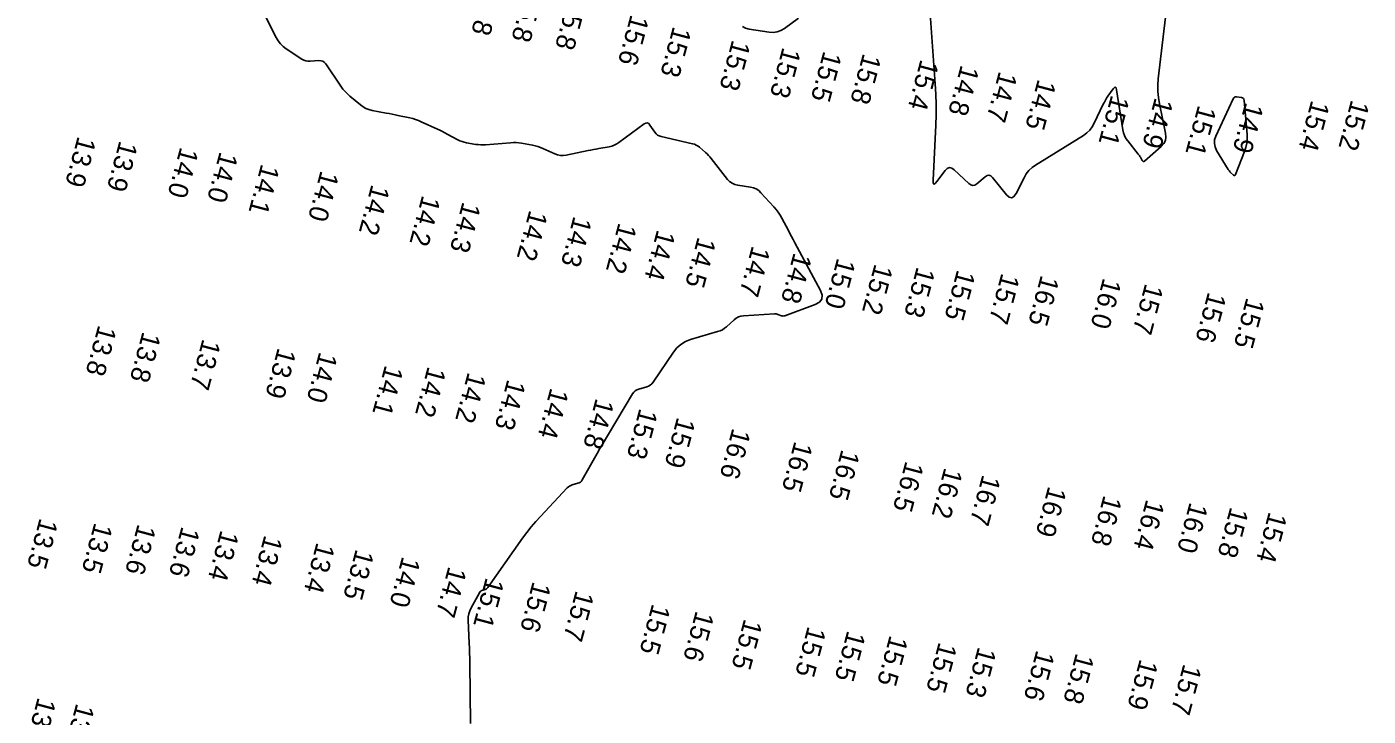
# Model space of a CAD drawing. Extents: x 988130 to 1132882, y 654656 to 841453.
# Drawn here: x 1028543.7 to 1028891.8, y 772126.1 to 772305 of the extents above; entities that cross this region are included whole.
import ezdxf

# ---------------------------------------------------------------- set-up
doc = ezdxf.new("R2010")
doc.units = 0
doc.layers.add('V-TOPO-MAJR', color=7, linetype='Continuous')
doc.layers.add('V-TOPO-SOUN', color=7, linetype='Continuous')

msp = doc.modelspace()

# ---------------------------------------------------------------- linework, layer by layer
at = {"layer": 'V-TOPO-MAJR'}
for points in [[(1028840.9, 772322.06), (1028837.3, 772291.48), (1028837.18, 772289.85), (1028837.19, 772288.22), (1028837.33, 772286.6), (1028837.6, 772284.98), (1028839.21, 772277.36), (1028839.3, 772276.38), (1028839.14, 772275.48), (1028838.73, 772274.67), (1028838.07, 772273.94), (1028833.74, 772270.14), (1028833.56, 772270.03), (1028833.4, 772270.01), (1028833.26, 772270.09), (1028833.13, 772270.26), (1028832.67, 772271.13), (1028832.55, 772271.35), (1028832.42, 772271.56), (1028832.28, 772271.76), (1028832.13, 772271.96), (1028829.38, 772275.38), (1028828.92, 772276.03), (1028828.56, 772276.73), (1028828.29, 772277.47), (1028828.12, 772278.25), (1028826.5, 772288.66), (1028826.38, 772289.11), (1028826.19, 772289.3), (1028825.94, 772289.22), (1028825.63, 772288.87), (1028824.24, 772286.95), (1028823.91, 772286.47), (1028823.6, 772285.97), (1028823.31, 772285.45), (1028823.05, 772284.92), (1028820.71, 772279.97), (1028820.18, 772279.02), (1028819.53, 772278.18), (1028818.76, 772277.43), (1028817.87, 772276.8), (1028805.47, 772269.11), (1028804.55, 772268.45), (1028803.74, 772267.68), (1028803.05, 772266.81), (1028802.47, 772265.83), (1028800.41, 772261.7), (1028799.86, 772260.91), (1028799.27, 772260.6), (1028798.62, 772260.77), (1028797.91, 772261.42), (1028794.29, 772265.87), (1028793.84, 772266.29), (1028793.37, 772266.46), (1028792.87, 772266.38), (1028792.35, 772266.06), (1028790.21, 772264.26), (1028789.68, 772263.93), (1028789.16, 772263.83), (1028788.64, 772263.96), (1028788.14, 772264.32), (1028784.36, 772267.89), (1028783.72, 772268.34), (1028783.11, 772268.46), (1028782.53, 772268.24), (1028781.98, 772267.69), (1028779.83, 772264.8), (1028779.37, 772264.29), (1028779.05, 772264.17), (1028778.88, 772264.46), (1028778.85, 772265.16), (1028779.57, 772279.44), (1028779.67, 772282.11), (1028779.68, 772284.79), (1028779.61, 772287.47), (1028779.45, 772290.14), (1028778.03, 772309.51)], [(1028602.75, 772313.44), (1028608.38, 772302.21), (1028608.89, 772301.35), (1028609.49, 772300.57), (1028610.18, 772299.89), (1028610.98, 772299.29), (1028615.09, 772296.6), (1028615.58, 772296.33), (1028616.1, 772296.15), (1028616.63, 772296.05), (1028617.19, 772296.05), (1028619.48, 772296.21), (1028620.02, 772296.18), (1028620.49, 772296.03), (1028620.91, 772295.75), (1028621.26, 772295.34), (1028625.22, 772289.53), (1028625.73, 772288.82), (1028626.29, 772288.16), (1028626.9, 772287.54), (1028627.55, 772286.96), (1028630.26, 772284.72), (1028630.95, 772284.21), (1028631.69, 772283.8), (1028632.48, 772283.49), (1028633.32, 772283.28), (1028636.93, 772282.61), (1028637.7, 772282.47), (1028638.47, 772282.32), (1028639.24, 772282.16), (1028640.01, 772282), (1028643.08, 772281.34), (1028643.84, 772281.16), (1028644.59, 772280.93), (1028645.32, 772280.66), (1028646.04, 772280.36), (1028650.24, 772278.42), (1028650.89, 772278.12), (1028651.53, 772277.8), (1028652.17, 772277.47), (1028652.81, 772277.14), (1028655.52, 772275.68), (1028656.07, 772275.41), (1028656.63, 772275.19), (1028657.22, 772275.01), (1028657.82, 772274.89), (1028660.25, 772274.48), (1028660.86, 772274.4), (1028661.47, 772274.36), (1028662.08, 772274.35), (1028662.69, 772274.38), (1028669.24, 772274.91), (1028669.95, 772274.95), (1028670.67, 772274.94), (1028671.38, 772274.88), (1028672.09, 772274.78), (1028674.92, 772274.27), (1028675.62, 772274.12), (1028676.31, 772273.93), (1028676.98, 772273.7), (1028677.64, 772273.42), (1028680.67, 772272.02), (1028681.4, 772271.75), (1028682.15, 772271.61), (1028682.91, 772271.58), (1028683.68, 772271.68), (1028689.37, 772272.86), (1028690.05, 772273), (1028690.73, 772273.13), (1028691.41, 772273.26), (1028692.1, 772273.38), (1028694.84, 772273.87), (1028695.51, 772274.03), (1028696.15, 772274.26), (1028696.76, 772274.57), (1028697.33, 772274.94), (1028703.88, 772279.76), (1028704.31, 772279.99), (1028704.7, 772280.02), (1028705.07, 772279.86), (1028705.39, 772279.49), (1028706.63, 772277.65), (1028706.97, 772277.23), (1028707.37, 772276.9), (1028707.82, 772276.65), (1028708.34, 772276.48), (1028716.47, 772274.64), (1028716.96, 772274.49), (1028717.43, 772274.29), (1028717.87, 772274.03), (1028718.27, 772273.71), (1028719.85, 772272.33), (1028720.23, 772271.98), (1028720.6, 772271.61), (1028720.95, 772271.22), (1028721.28, 772270.82), (1028725.53, 772265.4), (1028726.08, 772264.82), (1028726.7, 772264.37), (1028727.41, 772264.05), (1028728.19, 772263.86), (1028731.46, 772263.39), (1028732.24, 772263.2), (1028732.96, 772262.9), (1028733.62, 772262.47), (1028734.21, 772261.93), (1028737.57, 772258.25), (1028738.16, 772257.57), (1028738.69, 772256.86), (1028739.18, 772256.11), (1028739.63, 772255.33), (1028741.31, 772252.15), (1028741.73, 772251.35), (1028742.15, 772250.55), (1028742.58, 772249.76), (1028743, 772248.96), (1028749.63, 772236.53), (1028750.07, 772235.33), (1028749.98, 772234.32), (1028749.38, 772233.52), (1028748.26, 772232.91), (1028740.42, 772230.02), (1028740.19, 772229.96), (1028739.96, 772229.94), (1028739.74, 772229.96), (1028739.51, 772230.02), (1028738.61, 772230.36), (1028738.38, 772230.43), (1028738.15, 772230.48), (1028737.92, 772230.5), (1028737.68, 772230.5), (1028729.65, 772229.98), (1028728.99, 772229.88), (1028728.38, 772229.69), (1028727.81, 772229.39), (1028727.29, 772228.99), (1028725.27, 772227.18), (1028724.75, 772226.76), (1028724.19, 772226.4), (1028723.59, 772226.12), (1028722.96, 772225.89), (1028715.92, 772223.81), (1028714.6, 772223.3), (1028713.42, 772222.59), (1028712.39, 772221.69), (1028711.5, 772220.58), (1028706.2, 772212.79), (1028705.87, 772212.38), (1028705.49, 772212.04), (1028705.05, 772211.78), (1028704.56, 772211.59), (1028702.48, 772210.98), (1028702, 772210.78), (1028701.57, 772210.51), (1028701.2, 772210.17), (1028700.89, 772209.74), (1028694.61, 772199.26), (1028693.87, 772198.03), (1028693.14, 772196.78), (1028692.42, 772195.54), (1028691.71, 772194.28), (1028687.82, 772187.43), (1028687.61, 772187.12), (1028687.35, 772186.87), (1028687.05, 772186.68), (1028686.7, 772186.55), (1028685.22, 772186.12), (1028684.86, 772185.99), (1028684.53, 772185.82), (1028684.22, 772185.61), (1028683.94, 772185.35), (1028676.96, 772177.97), (1028675.74, 772176.63), (1028674.56, 772175.24), (1028673.44, 772173.82), (1028672.36, 772172.35), (1028663.32, 772159.51), (1028663.18, 772159.34), (1028663.02, 772159.2), (1028662.84, 772159.09), (1028662.64, 772159), (1028661.8, 772158.71), (1028661.6, 772158.62), (1028661.43, 772158.5), (1028661.29, 772158.35), (1028661.16, 772158.17), (1028658.97, 772154.2), (1028658.62, 772153.45), (1028658.38, 772152.69), (1028658.25, 772151.9), (1028658.24, 772151.08), (1028658.5, 772145.05), (1028658.55, 772143.77), (1028658.59, 772142.49), (1028658.62, 772141.2), (1028658.64, 772139.92), (1028658.81, 772124.26)], [(1028743.93, 772307.24), (1028740.31, 772304.56), (1028739.39, 772304), (1028738.42, 772303.65), (1028737.4, 772303.51), (1028736.33, 772303.56), (1028731.16, 772304.32), (1028730.19, 772304.59), (1028729.43, 772305.09)]]:
    msp.add_lwpolyline(points, dxfattribs=at)
msp.add_lwpolyline([(1028857.09, 772286.71), (1028856.88, 772286.54), (1028856.73, 772286.29), (1028852.24, 772276.59), (1028851.93, 772275.65), (1028851.86, 772274.72), (1028852.03, 772273.81), (1028852.46, 772272.91), (1028855.47, 772267.98), (1028855.61, 772267.77), (1028855.76, 772267.58), (1028855.92, 772267.39), (1028856.09, 772267.21), (1028856.82, 772266.51), (1028856.99, 772266.39), (1028857.14, 772266.37), (1028857.26, 772266.45), (1028857.36, 772266.63), (1028859.71, 772272.58), (1028860.07, 772273.66), (1028860.3, 772274.76), (1028860.39, 772275.88), (1028860.36, 772277.01), (1028859.6, 772285.88), (1028859.53, 772286.17), (1028859.4, 772286.39), (1028859.19, 772286.53), (1028858.91, 772286.61), (1028857.63, 772286.79), (1028857.34, 772286.79)], close=True, dxfattribs=at)

# ---------------------------------------------------------------- texts
at = {"layer": 'V-TOPO-SOUN'}
for s, p in [('15.8 ', (1028662.35, 772316.11)), ('15.8 ', (1028672.77, 772314.37)), ('15.8 ', (1028684.1, 772312.35)), ('15.6 ', (1028700.42, 772308.33)), ('15.3 ', (1028711.42, 772305.27)), ('15.3 ', (1028726.77, 772301.78)), ('15.3 ', (1028739.85, 772299.86)), ('15.5 ', (1028750.47, 772298.88)), ('15.8 ', (1028760.71, 772298.26)), ('15.4 ', (1028775.66, 772296.72)), ('14.8 ', (1028786.12, 772295.27)), ('14.7 ', (1028796.01, 772293.63)), ('14.5 ', (1028806.1, 772291.57)), ('15.1 ', (1028825.13, 772287.49)), ('14.9 ', (1028836.47, 772286.81)), ('15.4 ', (1028877.06, 772286.12)), ('15.2 ', (1028887.4, 772286.23)), ('15.1 ', (1028847.68, 772284.83)), ('14.9 ', (1028859.92, 772285.57)), ('13.9 ', (1028556.94, 772276.76)), ('13.9 ', (1028567.76, 772275.59)), ('14.0 ', (1028583.54, 772273.97)), ('14.0 ', (1028593.78, 772272.77)), ('14.1 ', (1028604.56, 772269.59)), ('14.0 ', (1028619.97, 772267.86)), ('14.2 ', (1028633.17, 772264.27)), ('14.2 ', (1028646.32, 772261.45)), ('14.3 ', (1028656.8, 772259.75)), ('14.2 ', (1028674.15, 772257.61)), ('14.3 ', (1028685.62, 772256.04)), ('14.2 ', (1028697.28, 772254.32)), ('14.4 ', (1028707.29, 772252.53)), ('14.5 ', (1028717.84, 772250.65)), ('14.7 ', (1028731.91, 772248.35)), ('14.8 ', (1028742.73, 772246.57)), ('15.0 ', (1028754.03, 772245.19)), ('15.2 ', (1028763.74, 772243.66)), ('15.3 ', (1028774.69, 772242.9)), ('15.5 ', (1028785.15, 772242.15)), ('15.7 ', (1028796.65, 772241.24)), ('16.5 ', (1028806.89, 772240.74)), ('16.0 ', (1028823.04, 772240.02)), ('15.7 ', (1028833.94, 772238.56)), ('15.6 ', (1028850.26, 772236.37)), ('15.5 ', (1028860.22, 772234.91)), ('13.8 ', (1028562.28, 772227.78)), ('13.8 ', (1028573.76, 772226.08)), ('13.7 ', (1028589.32, 772224.18)), ('13.9 ', (1028608.87, 772221.9)), ('14.0 ', (1028619.62, 772220.83)), ('14.1 ', (1028636.68, 772217.39)), ('14.2 ', (1028647.77, 772217.05)), ('14.2 ', (1028658.19, 772215.56)), ('14.3 ', (1028668.44, 772213.71)), ('14.4 ', (1028679.61, 772211.49)), ('14.8 ', (1028691.39, 772208.8)), ('15.3 ', (1028702.71, 772206.18)), ('15.9 ', (1028712.48, 772203.89)), ('16.6 ', (1028726.83, 772201.04)), ('16.5 ', (1028742.94, 772197.64)), ('16.5 ', (1028755.14, 772195.53)), ('16.5 ', (1028771.76, 772192.5)), ('16.2 ', (1028781.84, 772190.8)), ('16.7 ', (1028791.7, 772188.98)), ('16.9 ', (1028808.8, 772185.98)), ('16.8 ', (1028823.17, 772183.64)), ('16.4 ', (1028834.23, 772182.58)), ('16.0 ', (1028845.5, 772181.82)), ('13.5 ', (1028547.07, 772177.71)), ('15.8 ', (1028856.03, 772180.59)), ('15.4 ', (1028866.04, 772179.34)), ('13.5 ', (1028561.27, 772176.53)), ('13.6 ', (1028572.51, 772176.18)), ('13.6 ', (1028583.89, 772175.55)), ('13.4 ', (1028594.03, 772174.59)), ('13.4 ', (1028605.38, 772173.29)), ('13.4 ', (1028618.93, 772171.4)), ('13.5 ', (1028629.1, 772169.65)), ('14.0 ', (1028641.13, 772167.77)), ('14.7 ', (1028653.13, 772165.17)), ('15.1 ', (1028662.85, 772162.3)), ('15.6 ', (1028675.02, 772161.26)), ('15.7 ', (1028686.19, 772158.93)), ('15.5 ', (1028706.01, 772155.49)), ('15.6 ', (1028717.34, 772153.65)), ('15.5 ', (1028729.87, 772151.57)), ('15.5 ', (1028746.4, 772149.65)), ('15.5 ', (1028756.65, 772148.53)), ('15.5 ', (1028767.66, 772147.32)), ('15.5 ', (1028780.39, 772145.55)), ('15.3 ', (1028790.59, 772144.32)), ('15.6 ', (1028805.72, 772143.45)), ('15.8 ', (1028815.98, 772142.68)), ('15.9 ', (1028832.56, 772141.14)), ('15.7 ', (1028843.87, 772139.88)), ('13.7 ', (1028546.57, 772131.19)), ('13.9 ', (1028556.56, 772129.65))]:
    msp.add_text(s, height=5, rotation=255, dxfattribs=at).set_placement(p)

doc.saveas('drawing.dxf')
